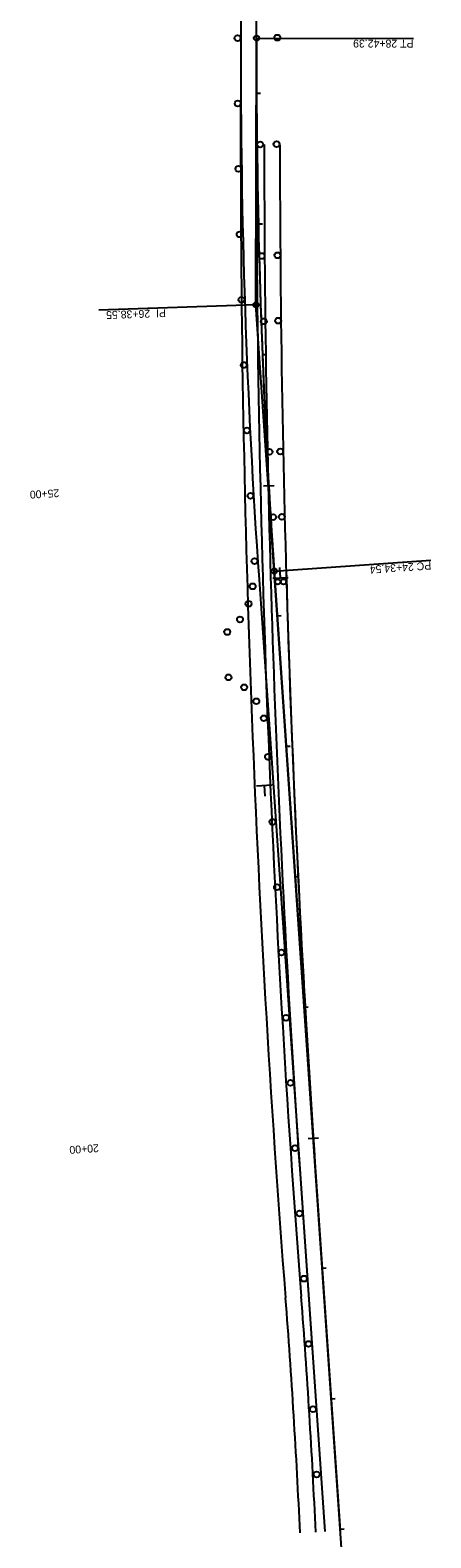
# Model space of a CAD drawing. Extents: x 1665984 to 1683035, y 227404 to 233856.
# Drawn here: x 1677130 to 1677436, y 231605 to 232758 of the extents above; entities that cross this region are included whole.
import ezdxf

# ---------------------------------------------------------------- set-up
doc = ezdxf.new("R2010")
doc.units = 0
for name, color, linetype in [('Default', 7, 'Continuous'), ('Level 47', 7, 'Continuous'), ('R_Horz Alg', 7, 'Continuous'), ('R_Horz Alg Annot', 7, 'Continuous'), ('R_Striping', 7, 'Continuous'), ('S_EDGE_PAVEMENT', 7, 'Continuous')]:
    doc.layers.add(name, color=color, linetype=linetype)

msp = doc.modelspace()

# ---------------------------------------------------------------- linework, layer by layer
at = {"layer": 'Default'}
for p, q in [((1677321.3, 232338.8), (1677320.8, 232346.9)), ((1677327.2, 232339), (1677315.4, 232338.3)), ((1677303.1, 232179.8), (1677314.9, 232180.6)), ((1677309, 232180), (1677309.5, 232172))]:
    msp.add_line(p, q, dxfattribs=at)
at = {"layer": 'Level 47'}
for centre, radius in [((1677288.6, 232751.6), 2.25), ((1677319, 232751.9), 2.25), ((1677288.7, 232701.6), 2.25), ((1677305.9, 232670.3), 2.25), ((1677318.4, 232670.5), 2.25), ((1677289.2, 232651.6), 2.25), ((1677290.2, 232601.5), 2.25), ((1677307, 232585), 2.25), ((1677319.1, 232585.5), 2.25), ((1677291.6, 232551.5), 2.25), ((1677308.6, 232535), 2.25), ((1677319.6, 232535.5), 2.25), ((1677293.4, 232501.6), 2.25), ((1677295.7, 232451.6), 2.25), ((1677313, 232435.2), 2.25), ((1677321.2, 232435.5), 2.25), ((1677298.4, 232401.6), 2.25), ((1677315.8, 232385.3), 2.25), ((1677322.4, 232385.5), 2.25), ((1677301.5, 232351.7), 2.25), ((1677300.1, 232332.4), 2.25), ((1677319.3, 232335.8), 2.02), ((1677323.7, 232335.9), 2.02), ((1677297, 232319.1), 2.25), ((1677290.4, 232307.1), 2.25), ((1677280.7, 232297.5), 2.25), ((1677281.7, 232262.8), 2.25), ((1677293.6, 232255.2), 2.25), ((1677302.9, 232244.5), 2.25), ((1677308.6, 232231.5), 2.25), ((1677311.8, 232202.1), 2.25), ((1677315.3, 232152.2), 2.25), ((1677318.7, 232102.3), 2.25), ((1677322.1, 232052.4), 2.25), ((1677325.6, 232002.5), 2.25), ((1677329, 231952.7), 2.25), ((1677332.5, 231902.8), 2.25), ((1677335.9, 231852.9), 2.25), ((1677339.3, 231803), 2.25), ((1677342.8, 231753.1), 2.25), ((1677346.2, 231703.2), 2.25), ((1677349, 231653.3), 2.25)]:
    msp.add_circle(centre, radius, dxfattribs=at)
at = {"layer": 'R_Horz Alg'}
for p, q in [((1677303.1, 232751.6), (1677305.7, 233853.8)), ((1677417.6, 230877), (1677316.6, 232344.1))]:
    msp.add_line(p, q, dxfattribs=at)
msp.add_arc((1683032.6, 232737.8), 5729.6, 179.86154, 183.94011, dxfattribs=at)
at = {"layer": 'R_Horz Alg Annot'}
for p, q in [((1677302.6, 232547.6), (1677303.1, 232751.6)), ((1677316.6, 232344.1), (1677302.6, 232547.6))]:
    msp.add_line(p, q, dxfattribs=at)
for points in [[(1677303.1, 232751.6), (1677423.1, 232751.3)], [(1677306.1, 232709.2), (1677303.1, 232709.2)], [(1677307.5, 232609.3), (1677304.5, 232609.2)], [(1677302.6, 232547.6), (1677182.6, 232543.6)], [(1677310.6, 232509.4), (1677307.6, 232509.3)], [(1677308.5, 232409.2), (1677316.5, 232409.6)], [(1677316.6, 232344.1), (1677436.3, 232352.3)], [(1677322, 232309.8), (1677319, 232309.6)], [(1677328.8, 232210), (1677325.8, 232209.8)], [(1677335.7, 232110.3), (1677332.7, 232110.1)], [(1677342.6, 232010.5), (1677339.6, 232010.3)], [(1677342.5, 231910.3), (1677350.4, 231910.8)], [(1677356.3, 231811), (1677353.3, 231810.8)], [(1677363.2, 231711.2), (1677360.2, 231711)], [(1677370.1, 231611.5), (1677367.1, 231611.3)]]:
    msp.add_lwpolyline(points, dxfattribs=at)
for centre in [(1677303.1, 232751.6), (1677302.6, 232547.6), (1677316.6, 232344.1)]:
    msp.add_circle(centre, 2, dxfattribs=at)
at = {"layer": 'R_Striping'}
for p, q in [((1677316.6, 232344.1), (1677367.1, 231610.5)), ((1677305, 232337.6), (1677355.2, 231609.6))]:
    msp.add_line(p, q, dxfattribs=at)
for centre, radius, start, end in [((1683032.6, 232737.8), 5741.6, 179.86154, 183.99693), ((1683032.6, 232737.8), 5729.6, 180.67519, 183.94011), ((1688792.1, 232675.8), 11471.2, 181.6543, 183.94011)]:
    msp.add_arc(centre, radius, start, end, dxfattribs=at)
at = {"layer": 'S_EDGE_PAVEMENT'}
for p, q in [((1677293.7, 233853.9), (1677291, 232703.6)), ((1677336.1, 231886.8), (1677355.2, 231609.6))]:
    msp.add_line(p, q, dxfattribs=at)
for centre, radius, start, end in [((1688792.1, 232675.8), 11501.2, 179.86154, 184.42552), ((1688792.1, 232675.8), 11489.2, 180.02731, 184.42552), ((1688792.1, 232675.8), 11483.2, 180.02731, 183.94011), ((1688792.1, 232675.8), 11471.2, 180.02731, 183.94011), ((1671600.8, 231345.3), 5741.6, 2.62807, 4.42552), ((1671600.8, 231345.3), 5753.6, 2.62807, 4.42552)]:
    msp.add_arc(centre, radius, start, end, dxfattribs=at)

# ---------------------------------------------------------------- texts
at = {"layer": 'R_Horz Alg Annot'}
for s, rotation, p in [('PT 28+42.39', 179.8615, (1677423.1, 232750.3)), ('PI  26+38.55', 181.9008, (1677233.7, 232544.3)), ('25+00', 183.2855, (1677152.1, 232406.7)), ('PC 24+34.54', 183.9401, (1677436.4, 232351.3)), ('20+00', 183.9401, (1677182.3, 231905.9))]:
    msp.add_text(s, height=6, rotation=rotation, dxfattribs=at).set_placement(p)

doc.saveas('drawing.dxf')
